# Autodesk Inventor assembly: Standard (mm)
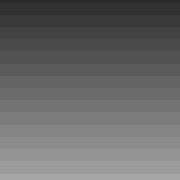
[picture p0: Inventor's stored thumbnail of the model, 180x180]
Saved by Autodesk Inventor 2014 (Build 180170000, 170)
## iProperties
Shininess: 64.0
Length Units: 11269
Angle Units: 11279
Time Units: 11290
Mass Units: 11283
Length Display Precision: 3
Angle Display Precision: 2
Compacted: True
Created: 2002-07
Part Number: Standard (mm)
Document SubType Name: Assembly
Density: 0.0
Volumn: 0.0
Area: 0.0
PropertySet Name: Model Information
Control State: 0
Master: False
Checked Out: False
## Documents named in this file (1)
- C:\Documents and Settings\administrator\Local Settings\My Documents\Vault\Templates\Customised - BOM.iam
